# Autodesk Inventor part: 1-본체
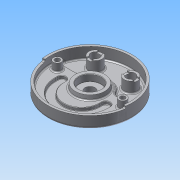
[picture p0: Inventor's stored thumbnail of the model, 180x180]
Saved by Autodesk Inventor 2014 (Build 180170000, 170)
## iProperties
Created: 2015-06
Part Number: 1-본체
Material: 알루미늄 6061
Document SubType Name: Modeling
Designer: Administrator
Density: 2.71 g/cm^3
Appearance: 알루미늄 - 평지
Mass: 1071.77 g
Surface Area: 1034.19 cm^2
Volume: 395.488 cm^3
Author: Administrator
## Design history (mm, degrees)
sketch "스케치1"
  geometry: C1 r 95 at (0, 0); 1 further point
  constraints: 1 centre point, 1 coincident
  dimensions: "d0" = 190 diameter of C1
extrude "돌출1" new body sketch "스케치1" distance "d1" = 32; taper "d2" = 0 deg
feature "쉘1" dims "d3" = 7, "d4" = 5
sketch "스케치2"
  geometry: L1 (38.833, 16)-(75.657, 16); L2 (-38.833, 16)-(-75.657, 16); A1 r 90 centre (0, 0) between (88.566, 16) and (-88.566, 16) reference; A2 r 42 centre (0, 0) between (38.833, 16) and (-38.833, 16); A3 r 90 centre (0, 0) between (85.114, 29.25) and (-85.114, 29.25); A4 r 10 centre (-75.657, 26) between (-85.114, 29.25) and (-75.657, 16); A5 r 10 centre (75.657, 26) between (75.657, 16) and (85.114, 29.25)
  constraints: 12 point on circle, 4 centre point, 4 end point, 4 tangent, 2 coincident, 2 collinear, 2 point on line, 1 equal radius, 1 horizontal
  dimensions: "d5" = 84 diameter of A2; "d6" = 16 distance from line of A1.centre L1; "d7" = 10 radius of A4
extrude "돌출2" join sketch "스케치2" distance "d8" = 7; taper "d9" = 0 deg
sketch "스케치3"
  geometry: C1 r 35 at (0, 0); A1 r 90 centre (0, 0) between (-85.114, 29.25) and (85.114, 29.25) reference
  constraints: 1 centre point, 1 coincident
  dimensions: "d10" = 70 diameter of C1
extrude "돌출3" join sketch "스케치3" distance "d11" = 10; taper "d12" = -10 deg
sketch "스케치4"
  geometry: C1 r 95 at (0, 0) reference; C2 r 26 at (0, 0)
  constraints: 1 centre point, 1 coincident
  dimensions: "d13" = 52 diameter of C2
extrude "돌출4" join sketch "스케치4" distance "d14" = 12; taper "d15" = -15 deg
hole "구멍1" diameter "d18" = 23; stored, may be unused: countersink angle "d22" = 90 deg, drill point angle "d24" = 118 deg; dims "d16" = 10, "d17" = 10, "d19" = 6, "d20" = 50, "d21" = 15, "d23" = 8
sketch "스케치5"
  geometry: L1 (-38.833, 16)-(-75.657, 16) reference; L2 (-59, -19)-(-59, -14); L3 (-41, -19)-(-41, -14); L4 (41, -19)-(41, -14); L5 (59, -19)-(59, -14); C1 r 35 at (0, 0) reference; A1 r 41 centre (0, -19) between (-41, -19) and (41, -19); A2 r 59 centre (0, -19) between (-59, -19) and (59, -19); A3 r 9 centre (-50, -14) between (-41, -14) and (-59, -14); A4 r 9 centre (50, -14) between (59, -14) and (41, -14); 1 further point
  constraints: 8 end point, 8 point on circle, 8 tangent, 6 parallel, 4 centre point, 2 coincident, 1 perpendicular, 1 vertical alignment
  dimensions: "d25" = 19 distance of A2.centre C1.centre; "d28" = 41 radius of A1; "d29" = 59 radius of A2; "d30" = 5 distance of L2.start L2.end
extrude "돌출5" cut sketch "스케치5" distance "d31" = 7; taper "d32" = 0 deg
sketch "스케치6"
  geometry: L1 (0, 133)-(0, -133) reference; C1 r 15 at (-40, 52); C2 r 15 at (40, 52); A1 r 42 centre (0, 0) between (38.833, 16) and (-38.833, 16) reference
  constraints: 2 centre point, 1 equal radius, 1 horizontal alignment, 1 other
  dimensions: "d33" = 30 diameter of C1; "d34" = 52 vertical distance of A1.centre C2.centre; "d35" = 80 distance of C2.centre C1.centre
extrude "돌출6" join sketch "스케치6" distance "d36" = 25; taper "d37" = 0 deg
sketch "스케치7"
  geometry: L1 (6, -17.5)-(-6, -17.5); L2 (-6, -17.5)-(-6, 17.5); L3 (-6, 17.5)-(6, 17.5); L4 (6, 17.5)-(6, -17.5); L5 (6, -17.5)-(-6, 17.5); L6 (-6, -17.5)-(6, 17.5); L7 (97.5, -6)-(62.5, -6); L8 (62.5, -6)-(62.5, 6); L9 (62.5, 6)-(97.5, 6); L10 (97.5, 6)-(97.5, -6); L11 (97.5, -6)-(62.5, 6); L12 (62.5, -6)-(97.5, 6); C1 r 15 at (0, 0) reference; C2 r 15 at (80, 0) reference; 1 further point
  constraints: 24 end point, 4 midpoint, 4 parallel, 4 perpendicular, 2 horizontal
  dimensions: "d38" = 12 distance of L2.end L3.end; "d39" = 35 distance of L3.end L1.start
extrude "돌출7" cut sketch "스케치7" distance "d40" = 3; taper "d41" = 0 deg
sketch "스케치8"
  geometry: L1 (26.252, 58)-(53.748, 58) reference; A1 r 15 centre (-40, 52) between (-46, 65.748) and (-46, 38.252) reference; A2 r 15 centre (40, 52) between (53.748, 58) and (26.252, 58) reference; 3 further points
  constraints: 2 coincident
hole "구멍2" sketch "스케치8" at (-40, 52), (40, 52) diameter "d42" = 20; stored, may be unused: countersink angle "d46" = 90 deg, drill point angle "d48" = 118 deg; dims "d43" = 6, "d44" = 50, "d45" = 15, "d47" = 8
sketch "스케치9"
  geometry: L1 (0, 133)-(0, -133) reference; C1 r 35 at (0, 0) reference; C2 r 9 at (-74, 0); C3 r 9 at (74, 0)
  constraints: 2 centre point, 1 equal radius, 1 horizontal alignment, 1 other
  dimensions: "d49" = 18 diameter of C2; "d50" = 148 distance of C3.centre C2.centre
extrude "돌출8" join sketch "스케치9" distance "d51" = 18; taper "d52" = 0 deg
sketch "스케치10"
  geometry: C1 r 9 at (74, 0) reference; C2 r 9 at (-74, 0) reference; 2 further points
  constraints: 2 coincident
hole "구멍3" sketch "스케치10" at (-74, 0), (74, 0) diameter "d53" = 11; stored, may be unused: countersink angle "d57" = 90 deg, drill point angle "d59" = 118 deg; dims "d54" = 6, "d55" = 18, "d56" = 11, "d58" = 8
sketch "스케치11"
  geometry: L1 (0, 0)-(-89.124, -12.526); L2 (-133, 0)-(133, 0) reference; L3 (0, 0)-(89.124, -12.526); L4 (-89.124, -12.526)-(-94.075, -13.221); L5 (89.124, -12.526)-(94.075, -13.221); A1 r 90 centre (0, 0) between (-89.124, -12.526) and (89.124, -12.526) reference; A2 r 95 centre (0, 0) between (-94.075, -13.221) and (94.075, -13.221) reference; A3 r 95 centre (0, 0) between (-94.075, -13.221) and (94.075, -13.221); A4 r 90 centre (0, 0) between (-89.124, -12.526) and (89.124, -12.526)
  constraints: 8 end point, 8 point on circle, 2 centre point, 2 coincident, 2 collinear
  dimensions: "d60" = 8 deg angle of L1 L2; "d61" = 8 deg angle of L3 L2
extrude "돌출9" cut sketch "스케치11" distance "d62" = 5; taper "d63" = 0 deg
chamfer "모따기1" distance "d64" = 1; stored, may be unused: second distance "d65" = 2, angle "d66" = 45 deg
fillet "모깎기1" dims "d67" = 0.3
fillet "모깎기2" dims "d68" = 5
fillet "모깎기3" dims "d69" = 1
fillet "모깎기4" dims "d70" = 3
fillet "모깎기5" dims "d71" = 3
fillet "모깎기8" dims "d74" = 3
fillet "모깎기9" dims "d75" = 3
sketch "스케치12"
  geometry: C1 r 28.302 at (0, 0) reference; C2 r 68 at (0, 0)
  constraints: 1 centre point, 1 coincident, 1 other
  dimensions: "d76" = 136 diameter of C2
feature "엠보싱1" sketch "스케치12" dims "d77" = 0.5, "d78" = 0
fillet "모깎기13" dims "d82" = 10
fillet "모깎기14" dims "d83" = 3
node "솔리드1"
node "투영된 루프1"
node "투영된 루프2"
other parameters: "d26" = 118, "d27" = 82
